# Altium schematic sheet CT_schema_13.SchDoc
size 281 x 153 mm
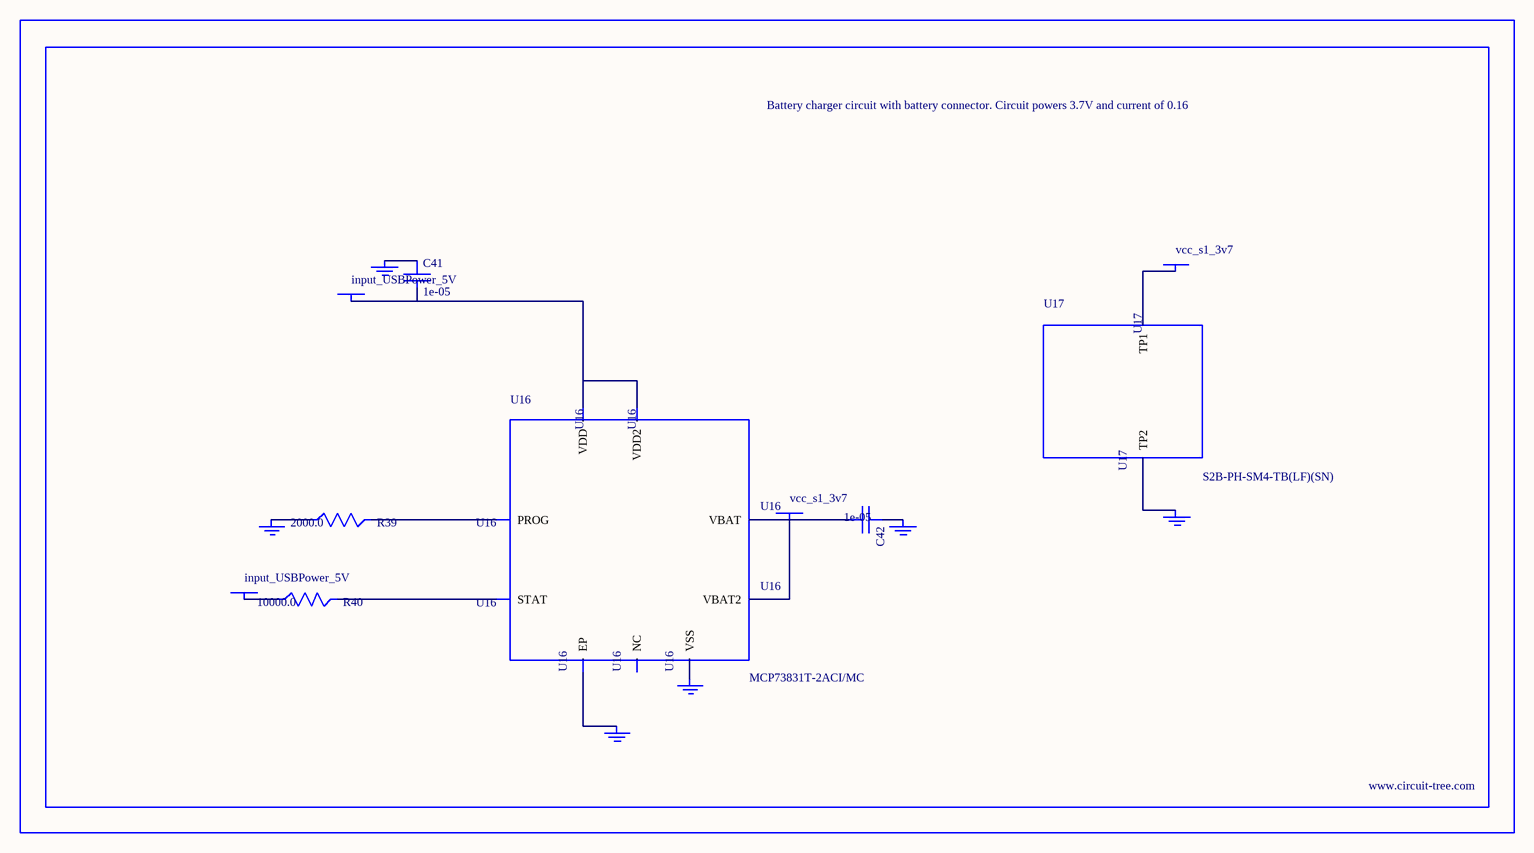
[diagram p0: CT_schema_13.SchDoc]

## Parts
BORDER12  (no value)
C41  1e-05  [C1206]
C42  1e-05  [C1206]
GND_INSTANCE_12_0  (no value)
GND_INSTANCE_12_1  (no value)
GND_INSTANCE_12_2  (no value)
GND_INSTANCE_12_3  (no value)
GND_INSTANCE_12_4  (no value)
GND_INSTANCE_12_5  (no value)
POWER_INSTANCE_12_0  input_USBPower_5V
POWER_INSTANCE_12_1  input_USBPower_5V
POWER_INSTANCE_12_2  vcc_s1_3v7
POWER_INSTANCE_12_3  vcc_s1_3v7
R39  2000.0  [R0603]
R40  10000.0  [R0603]
U16  MCP73831T-2ACI/MC  [DFN8_2X3MC]
U17  S2B-PH-SM4-TB(LF)(SN)  [JST-2-SMD]

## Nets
NetC41_1: C41.1 GND_INSTANCE_12_0.0(GND)
NetC41_2: C41.2 POWER_INSTANCE_12_0.0(PWR) U16.1(VDD) U16.2(VDD2)
NetC42_1: C42.1 GND_INSTANCE_12_1.0(GND)
NetC42_2: C42.2 POWER_INSTANCE_12_2.0(PWR) U16.3(VBAT) U16.4(VBAT2)
NetGND_INSTANCE_12_2_0: GND_INSTANCE_12_2.0(GND) R39.1
NetGND_INSTANCE_12_3_0: GND_INSTANCE_12_3.0(GND) U16.9(EP)
NetGND_INSTANCE_12_4_0: GND_INSTANCE_12_4.0(GND) U16.6(VSS)
NetGND_INSTANCE_12_5_0: GND_INSTANCE_12_5.0(GND) U17.2(TP2)
NetPOWER_INSTANCE_12_1_0: POWER_INSTANCE_12_1.0(PWR) R40.1
NetPOWER_INSTANCE_12_3_0: POWER_INSTANCE_12_3.0(PWR) U17.1(TP1)
NetR39_2: R39.2 U16.8(PROG)
NetR40_2: R40.2 U16.5(STAT)

Not connected (* = marked no-connect by the designer): U16 7(NC)

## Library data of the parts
BORDER12 = BORDER_PAGE12
C41 C42 = C1206C106K3RACTU
GND_INSTANCE_12_0-GND_INSTANCE_12_5 = GND
POWER_INSTANCE_12_0-POWER_INSTANCE_12_3 = PWR
R39 = RC0603JR-072KL
R40 = RC0603JR-0710KL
